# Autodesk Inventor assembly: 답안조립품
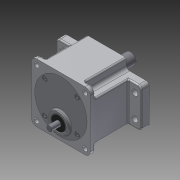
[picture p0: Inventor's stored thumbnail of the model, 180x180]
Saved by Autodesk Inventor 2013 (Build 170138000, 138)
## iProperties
Created: 2015-07
Part Number: 답안조립품
Document SubType Name: Assembly
Designer: user
Author: user
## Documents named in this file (12)
- C:\Users\user\Desktop\450734V1007\답안조립품.iam
- C:\Users\user\Desktop\450734V1007\본체.ipt
- C:\Users\user\Desktop\450734V1007\메인축.ipt
- C:\Users\user\Desktop\450734V1007\베어링 6003.ipt
- 베어링 6003.ipt
- C:\Users\user\Desktop\450734V1007\베어링 608.ipt
- 베어링 608.ipt
- C:\Users\user\Desktop\450734V1007\서브축.ipt
- C:\Users\user\Desktop\450734V1007\오일실 17x32x8.ipt
- C:\Users\user\Desktop\450734V1007\커버.ipt
- C:\Users\user\Desktop\450734V1007\오일실 8x22x7.ipt
- C:\Users\user\Desktop\450734V1007\M4x0.5x16.ipt
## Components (4 placed, 1 different names)
1. M4x0.5x12:1 — 각도:1
2. M4x0.5x12:2
3. M4x0.5x12:3
4. M4x0.5x12:4
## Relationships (1: Angle 1)
- 각도:1 [Angle]: M4x0.5x12:1
